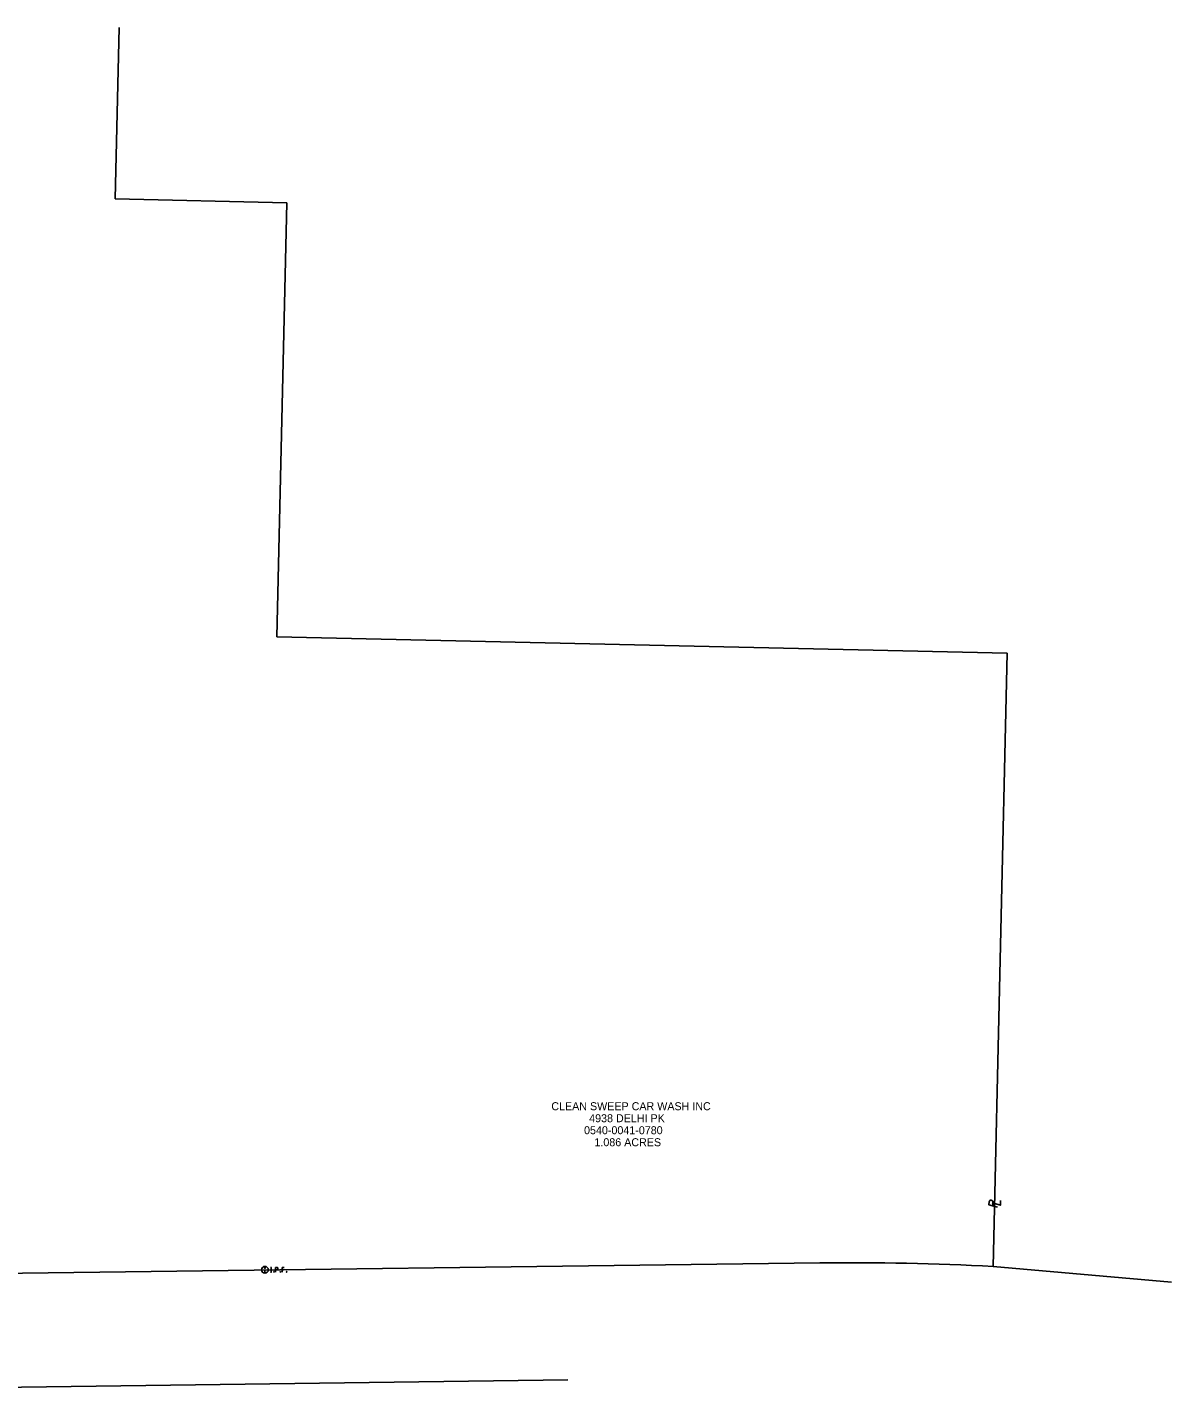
# Model space of a CAD drawing. Extents: x 1369159 to 1370720, y 404461 to 406422.
# Drawn here: x 1370319.7 to 1370719.7, y 405910.4 to 406390.1 of the extents above; entities that cross this region are included whole.
import ezdxf

# ---------------------------------------------------------------- set-up
doc = ezdxf.new("R2010")
doc.units = 0
for name, color, linetype in [('Default', 7, 'Continuous'), ('DR_P_Storm_Sewer', 7, 'Continuous'), ('GK_Drainage_Nodes', 7, 'Continuous'), ('SC_Scratch1', 7, 'Continuous'), ('XS_X_Pavt', 7, 'Continuous'), ('XS_X_Subgrade', 7, 'Continuous')]:
    doc.layers.add(name, color=color, linetype=linetype)

msp = doc.modelspace()

# ---------------------------------------------------------------- linework, layer by layer
at = {"layer": 'Default'}
for p, q in [((1370350.36, 406330.15), (1370351.7, 406390.11)), ((1370410.34, 406328.8), (1370350.36, 406330.15)), ((1370406.94, 406176.86), (1370410.34, 406328.8)), ((1370662.22, 406171.14), (1370406.94, 406176.86)), ((1370657.42, 405956.62), (1370662.22, 406171.14))]:
    msp.add_line(p, q, dxfattribs=at)
at = {"layer": 'DR_P_Storm_Sewer'}
for p, q in [((1370657.27, 405977.79), (1370657.3, 405979.09)), ((1370657.91, 405978.58), (1370657.91, 405978.58))]:
    msp.add_line(p, q, dxfattribs=at)
for points in [[(1370658.85, 405977.33), (1370655.9, 405978.18), (1370655.93, 405979.21)], [(1370656.96, 405978.86), (1370659.89, 405978.01), (1370659.93, 405979.75)]]:
    msp.add_lwpolyline(points, dxfattribs=at)
msp.add_arc((1370656.61, 405979.1), 0.69, 359.1878, 170.0449, dxfattribs=at)
at = {"layer": 'SC_Scratch1'}
for p, q in [((1370402.69, 405955.56), (1370402.69, 405954.68)), ((1370404.72, 405956.25), (1370405.07, 405956.25)), ((1370404.72, 405954.65), (1370405.07, 405954.65)), ((1370404.89, 405954.65), (1370404.89, 405956.25)), ((1370405.79, 405954.79), (1370405.82, 405954.84)), ((1370405.79, 405954.72), (1370405.79, 405954.79)), ((1370405.82, 405954.67), (1370405.79, 405954.72)), ((1370405.82, 405954.84), (1370405.85, 405954.86)), ((1370405.85, 405954.65), (1370405.82, 405954.67)), ((1370405.85, 405954.86), (1370405.91, 405954.86)), ((1370405.91, 405954.65), (1370405.85, 405954.65)), ((1370405.91, 405954.86), (1370405.94, 405954.84)), ((1370405.94, 405954.67), (1370405.91, 405954.65)), ((1370405.94, 405954.84), (1370405.97, 405954.79)), ((1370405.97, 405954.72), (1370405.94, 405954.67)), ((1370405.97, 405954.79), (1370405.97, 405954.72)), ((1370406.46, 405954.65), (1370406.46, 405956.25)), ((1370406.46, 405956.25), (1370406.99, 405956.25)), ((1370406.99, 405955.47), (1370406.46, 405955.47)), ((1370406.99, 405956.25), (1370407.04, 405956.24)), ((1370407.08, 405955.48), (1370406.99, 405955.47)), ((1370407.04, 405956.24), (1370407.12, 405956.21)), ((1370407.13, 405955.5), (1370407.08, 405955.48)), ((1370407.12, 405956.21), (1370407.15, 405956.18)), ((1370407.16, 405955.53), (1370407.13, 405955.5)), ((1370407.15, 405956.18), (1370407.19, 405956.16)), ((1370407.21, 405955.57), (1370407.16, 405955.53)), ((1370407.19, 405956.16), (1370407.23, 405956.1)), ((1370407.25, 405955.66), (1370407.21, 405955.57)), ((1370407.23, 405956.1), (1370407.26, 405956.03)), ((1370407.27, 405955.73), (1370407.25, 405955.66)), ((1370407.26, 405956.03), (1370407.29, 405955.93)), ((1370407.29, 405955.78), (1370407.27, 405955.73)), ((1370407.29, 405955.93), (1370407.29, 405955.78)), ((1370408.04, 405954.79), (1370408.07, 405954.84)), ((1370408.04, 405954.72), (1370408.04, 405954.79)), ((1370408.07, 405954.67), (1370408.04, 405954.72)), ((1370408.07, 405954.84), (1370408.1, 405954.86)), ((1370408.1, 405954.65), (1370408.07, 405954.67)), ((1370408.1, 405954.86), (1370408.16, 405954.86)), ((1370408.16, 405954.65), (1370408.1, 405954.65)), ((1370408.16, 405954.86), (1370408.19, 405954.84)), ((1370408.19, 405954.67), (1370408.16, 405954.65)), ((1370408.19, 405954.84), (1370408.22, 405954.79)), ((1370408.22, 405954.72), (1370408.19, 405954.67)), ((1370408.22, 405954.79), (1370408.22, 405954.72)), ((1370409.47, 405956.25), (1370408.71, 405956.25)), ((1370408.71, 405956.25), (1370408.71, 405954.65)), ((1370408.71, 405955.47), (1370409.25, 405955.47)), ((1370410.18, 405954.79), (1370410.22, 405954.84)), ((1370410.18, 405954.72), (1370410.18, 405954.79)), ((1370410.22, 405954.67), (1370410.18, 405954.72)), ((1370410.22, 405954.84), (1370410.25, 405954.86)), ((1370410.25, 405954.65), (1370410.22, 405954.67)), ((1370410.25, 405954.86), (1370410.31, 405954.86)), ((1370410.31, 405954.65), (1370410.25, 405954.65)), ((1370410.31, 405954.86), (1370410.34, 405954.84)), ((1370410.34, 405954.67), (1370410.31, 405954.65)), ((1370410.34, 405954.84), (1370410.37, 405954.79)), ((1370410.37, 405954.72), (1370410.34, 405954.67)), ((1370410.37, 405954.79), (1370410.37, 405954.72))]:
    msp.add_line(p, q, dxfattribs=at)
for centre, radius in [((1370402.69, 405955.45), 1.2), ((1370402.69, 405956.1), 0.16)]:
    msp.add_circle(centre, radius, dxfattribs=at)
at = {"layer": 'XS_X_Pavt'}
msp.add_line((1370023.59, 405910.4), (1370508.58, 405916.92), dxfattribs=at)
at = {"layer": 'XS_X_Subgrade'}
for p, q in [((1370070.19, 405951.11), (1370596.72, 405957.84)), ((1370719.74, 405951.18), (1370657.42, 405956.62))]:
    msp.add_line(p, q, dxfattribs=at)
msp.add_arc((1370608.52, 405036.44), 921.47, 86.95788, 90.73344, dxfattribs=at)

# ---------------------------------------------------------------- texts
at = {"layer": 'GK_Drainage_Nodes'}
for s, p in [('CLEAN SWEEP CAR WASH INC', (1370502.86, 406011.28)), ('4938 DELHI PK', (1370516.1, 406007.08)), ('0540-0041-0780', (1370514.31, 406002.88)), ('1.086 ACRES', (1370517.93, 405998.68))]:
    msp.add_text(s, height=2.8, dxfattribs=at).set_placement(p)

doc.saveas('drawing.dxf')
